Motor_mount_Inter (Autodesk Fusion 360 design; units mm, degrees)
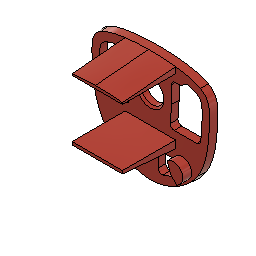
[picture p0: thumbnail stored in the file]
base_feature "Base Feature"
work_plane "WorkPlane1" AlongDistance -50.1
sketch "Sketch3" plane through (0, 0, -50.1) normal (0, 0, 1) x axis (1, 0, 0)
extrude "Extrude1" new body sketch "Sketch3" along normal blind 2 taper -5
sketch "Sketch4" plane through (0, 0, -48.1) normal (0, 0, 1) x axis (1, 0, 0)
  dimension "d89" = 2
extrude "Extrude2" add sketch "Sketch4" along normal blind 14
draft "Draft1" Angle1 5 Angle2 0
sketch "Sketch5" plane through (0, 0, -48.1) normal (0, 0, 1) x axis (1, 0, 0)
extrude "Extrude3" cut sketch "Sketch5" no distance stored
chamfer "Chamfer1" distance 0.5
draft "Draft2" Angle1 5 Angle2 0
sketch "Sketch6" plane through (0, 0, -48.1) normal (0, 0, 1) x axis (1, 0, 0)
  dimension "d101" = 2
  dimension "d102" = 2.5
extrude "Extrude4" cut sketch "Sketch6" no distance stored
fillet "Fillet1" radius 1
sketch "Sketch7" plane through (0, 0, -48.1) normal (0, 0, 1) x axis (1, 0, 0)
  dimension "d141" = 4
  dimension "d143" = 4
  dimension "d144" = 2.5
extrude "Extrude5" add sketch "Sketch7" along normal blind 2.5
fillet "Fillet2" radius 1
sketch "Sketch8" plane through (4.0871, 0, 0) normal (1, 0, 0) x axis (0, 0, -1)
sketch "Sketch9" plane through (4.0871, 0, 0) normal (1, 0, 0) x axis (0, 0, -1)
  dimension "d148" = 0.4
  dimension "d149" = 0.8
extrude "Extrude6" cut sketch "Sketch9" to an object
sketch "Sketch10" plane through (0, 0, -48.1) normal (0, 0, 1) x axis (1, 0, 0)
  dimension "d154" = 29.9506
  dimension "d155" = 26.0609
  dimension "d161" = 2.5
  dimension "d162" = 3.5
extrude "Extrude7" add sketch "Sketch10" along normal blind 0.8
sketch "Sketch11" plane through (0, 0, -47.3) normal (0, 0, 1) x axis (1, 0, 0)
  dimension "d164" = 1
extrude "Extrude8" add sketch "Sketch11" along normal blind 1.5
